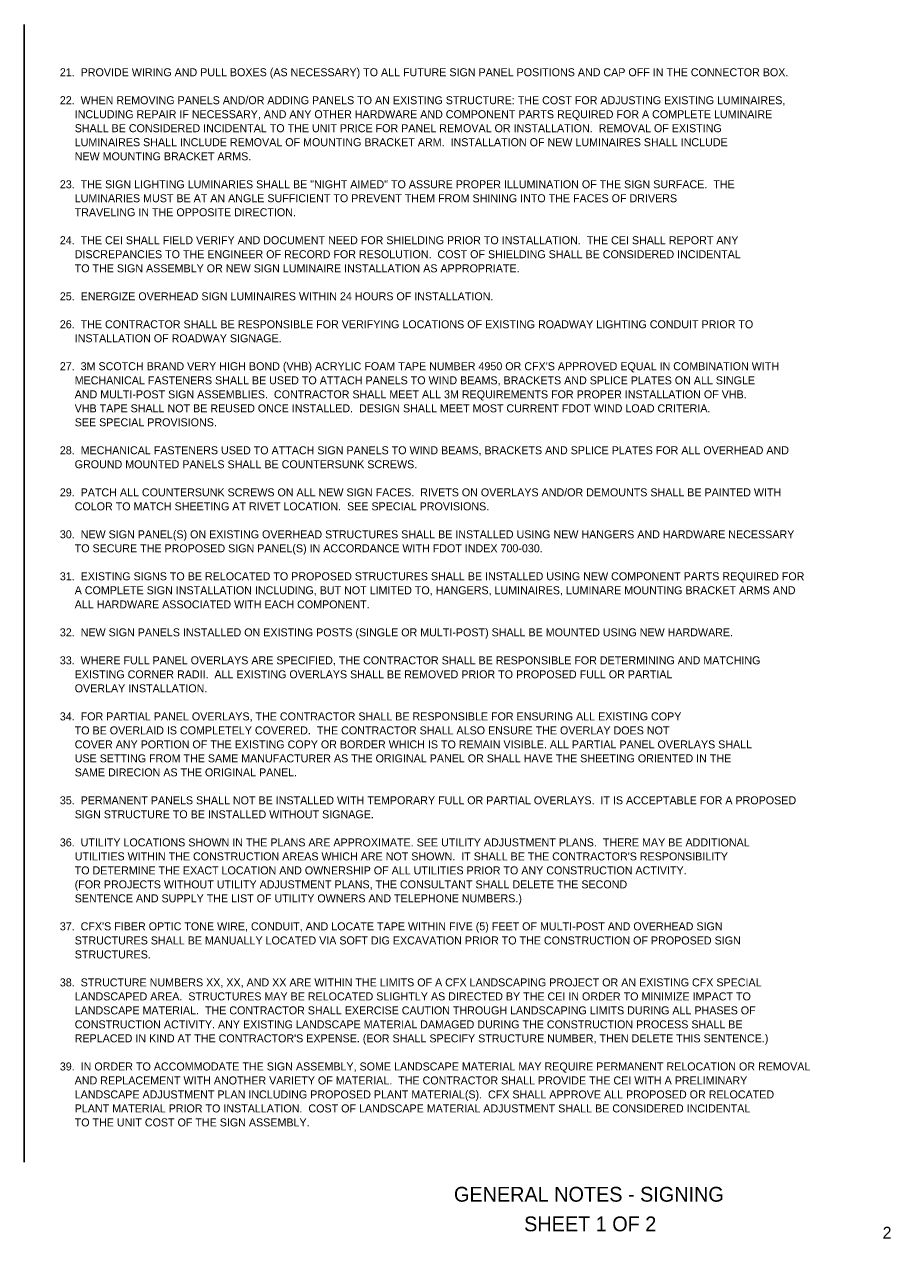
# Model space of a CAD drawing. Extents: x 2479946 to 2481502, y 3680184 to 3681234.
# Drawn here: x 2480771 to 2481502, y 3680210 to 3681234 of the extents above; entities that cross this region are included whole.
import ezdxf

# ---------------------------------------------------------------- set-up
doc = ezdxf.new("R2010")
doc.units = 0
for name, color, linetype in [('NonPlottingEle_dp', 7, 'Continuous'), ('TextLabel', 7, 'Continuous'), ('TextMisc', 7, 'Continuous'), ('TextShtNo', 7, 'Continuous')]:
    doc.layers.add(name, color=color, linetype=linetype)

msp = doc.modelspace()

# ---------------------------------------------------------------- linework, layer by layer
at = {"layer": 'NonPlottingEle_dp'}
msp.add_line((2480770.9, 3680274.2), (2480770.9, 3681234.2), dxfattribs=at)

# ---------------------------------------------------------------- texts
at = {"layer": 'TextLabel'}
for s, p in [('21.  PROVIDE WIRING AND PULL BOXES (AS NECESSARY) TO ALL FUTURE SIGN PANEL POSITIONS AND CAP OFF IN THE CONNECTOR BOX.', (2480800.9, 3681190.4)), ('22.  WHEN REMOVING PANELS AND/OR ADDING PANELS TO AN EXISTING STRUCTURE: THE COST FOR ADJUSTING EXISTING LUMINAIRES,', (2480800.9, 3681166.8)), ('     INCLUDING REPAIR IF NECESSARY, AND ANY OTHER HARDWARE AND COMPONENT PARTS REQUIRED FOR A COMPLETE LUMINAIRE', (2480800.9, 3681155)), ('     SHALL BE CONSIDERED INCIDENTAL TO THE UNIT PRICE FOR PANEL REMOVAL OR INSTALLATION.  REMOVAL OF EXISTING', (2480800.9, 3681143.2)), ('     LUMINAIRES SHALL INCLUDE REMOVAL OF MOUNTING BRACKET ARM.  INSTALLATION OF NEW LUMINAIRES SHALL INCLUDE', (2480800.9, 3681131.4)), ('     NEW MOUNTING BRACKET ARMS.', (2480800.9, 3681119.5)), ('23.  THE SIGN LIGHTING LUMINARIES SHALL BE "NIGHT AIMED" TO ASSURE PROPER ILLUMINATION OF THE SIGN SURFACE.  THE ', (2480800.9, 3681095.9)), ('     LUMINARIES MUST BE AT AN ANGLE SUFFICIENT TO PREVENT THEM FROM SHINING INTO THE FACES OF DRIVERS', (2480800.9, 3681084.1)), ('     TRAVELING IN THE OPPOSITE DIRECTION.', (2480800.9, 3681072.3)), ('24.  THE CEI SHALL FIELD VERIFY AND DOCUMENT NEED FOR SHIELDING PRIOR TO INSTALLATION.  THE CEI SHALL REPORT ANY', (2480800.9, 3681048.7)), ('     DISCREPANCIES TO THE ENGINEER OF RECORD FOR RESOLUTION.  COST OF SHIELDING SHALL BE CONSIDERED INCIDENTAL', (2480800.9, 3681036.9)), ('     TO THE SIGN ASSEMBLY OR NEW SIGN LUMINAIRE INSTALLATION AS APPROPRIATE.', (2480800.9, 3681025)), ('25.  ENERGIZE OVERHEAD SIGN LUMINAIRES WITHIN 24 HOURS OF INSTALLATION.', (2480800.9, 3681001.4)), ('26.  THE CONTRACTOR SHALL BE RESPONSIBLE FOR VERIFYING LOCATIONS OF EXISTING ROADWAY LIGHTING CONDUIT PRIOR TO', (2480800.9, 3680977.8)), ('     INSTALLATION OF ROADWAY SIGNAGE.', (2480800.9, 3680966)), ("27.  3M SCOTCH BRAND VERY HIGH BOND (VHB) ACRYLIC FOAM TAPE NUMBER 4950 OR CFX'S APPROVED EQUAL IN COMBINATION WITH", (2480800.9, 3680942.4)), ('     MECHANICAL FASTENERS SHALL BE USED TO ATTACH PANELS TO WIND BEAMS, BRACKETS AND SPLICE PLATES ON ALL SINGLE', (2480800.9, 3680930.5)), ('     AND MULTI-POST SIGN ASSEMBLIES.  CONTRACTOR SHALL MEET ALL 3M REQUIREMENTS FOR PROPER INSTALLATION OF VHB.', (2480800.9, 3680918.7)), ('     VHB TAPE SHALL NOT BE REUSED ONCE INSTALLED.  DESIGN SHALL MEET MOST CURRENT FDOT WIND LOAD CRITERIA.', (2480800.9, 3680906.9)), ('     SEE SPECIAL PROVISIONS.', (2480800.9, 3680895.1)), ('28.  MECHANICAL FASTENERS USED TO ATTACH SIGN PANELS TO WIND BEAMS, BRACKETS AND SPLICE PLATES FOR ALL OVERHEAD AND', (2480800.9, 3680871.5)), ('     GROUND MOUNTED PANELS SHALL BE COUNTERSUNK SCREWS.', (2480800.9, 3680859.7)), ('29.  PATCH ALL COUNTERSUNK SCREWS ON ALL NEW SIGN FACES.  RIVETS ON OVERLAYS AND/OR DEMOUNTS SHALL BE PAINTED WITH', (2480800.9, 3680836)), ('     COLOR TO MATCH SHEETING AT RIVET LOCATION.  SEE SPECIAL PROVISIONS.', (2480800.9, 3680824.2)), ('30.  NEW SIGN PANEL(S) ON EXISTING OVERHEAD STRUCTURES SHALL BE INSTALLED USING NEW HANGERS AND HARDWARE NECESSARY', (2480800.9, 3680800.6)), ('     TO SECURE THE PROPOSED SIGN PANEL(S) IN ACCORDANCE WITH FDOT INDEX 700-030.', (2480800.9, 3680788.8)), ('31.  EXISTING SIGNS TO BE RELOCATED TO PROPOSED STRUCTURES SHALL BE INSTALLED USING NEW COMPONENT PARTS REQUIRED FOR', (2480800.9, 3680765.2)), ('     A COMPLETE SIGN INSTALLATION INCLUDING, BUT NOT LIMITED TO, HANGERS, LUMINAIRES, LUMINARE MOUNTING BRACKET ARMS AND', (2480800.9, 3680753.4)), ('     ALL HARDWARE ASSOCIATED WITH EACH COMPONENT.', (2480800.9, 3680741.5)), ('32.  NEW SIGN PANELS INSTALLED ON EXISTING POSTS (SINGLE OR MULTI-POST) SHALL BE MOUNTED USING NEW HARDWARE.', (2480800.9, 3680717.9)), ('33.  WHERE FULL PANEL OVERLAYS ARE SPECIFIED, THE CONTRACTOR SHALL BE RESPONSIBLE FOR DETERMINING AND MATCHING', (2480800.9, 3680694.3)), ('     EXISTING CORNER RADII.  ALL EXISTING OVERLAYS SHALL BE REMOVED PRIOR TO PROPOSED FULL OR PARTIAL', (2480800.9, 3680682.5)), ('     OVERLAY INSTALLATION.', (2480800.9, 3680670.7)), ('34.  FOR PARTIAL PANEL OVERLAYS, THE CONTRACTOR SHALL BE RESPONSIBLE FOR ENSURING ALL EXISTING COPY', (2480800.9, 3680647)), ('     TO BE OVERLAID IS COMPLETELY COVERED.  THE CONTRACTOR SHALL ALSO ENSURE THE OVERLAY DOES NOT ', (2480800.9, 3680635.2)), ('     COVER ANY PORTION OF THE EXISTING COPY OR BORDER WHICH IS TO REMAIN VISIBLE. ALL PARTIAL PANEL OVERLAYS SHALL', (2480800.9, 3680623.4)), ('     USE SETTING FROM THE SAME MANUFACTURER AS THE ORIGINAL PANEL OR SHALL HAVE THE SHEETING ORIENTED IN THE', (2480800.9, 3680611.6)), ('     SAME DIRECION AS THE ORIGINAL PANEL.', (2480800.9, 3680599.8)), ('35.  PERMANENT PANELS SHALL NOT BE INSTALLED WITH TEMPORARY FULL OR PARTIAL OVERLAYS.  IT IS ACCEPTABLE FOR A PROPOSED', (2480800.9, 3680576.2)), ('     SIGN STRUCTURE TO BE INSTALLED WITHOUT SIGNAGE.', (2480800.9, 3680564.4)), ('36.  UTILITY LOCATIONS SHOWN IN THE PLANS ARE APPROXIMATE. SEE UTILITY ADJUSTMENT PLANS.  THERE MAY BE ADDITIONAL', (2480800.9, 3680540.7)), ("     UTILITIES WITHIN THE CONSTRUCTION AREAS WHICH ARE NOT SHOWN.  IT SHALL BE THE CONTRACTOR'S RESPONSIBILITY", (2480800.9, 3680528.9)), ('     TO DETERMINE THE EXACT LOCATION AND OWNERSHIP OF ALL UTILITIES PRIOR TO ANY CONSTRUCTION ACTIVITY.', (2480800.9, 3680517.1)), ('     (FOR PROJECTS WITHOUT UTILITY ADJUSTMENT PLANS, THE CONSULTANT SHALL DELETE THE SECOND', (2480800.9, 3680505.3)), ('     SENTENCE AND SUPPLY THE LIST OF UTILITY OWNERS AND TELEPHONE NUMBERS.)', (2480800.9, 3680493.5)), ("37.  CFX'S FIBER OPTIC TONE WIRE, CONDUIT, AND LOCATE TAPE WITHIN FIVE (5) FEET OF MULTI-POST AND OVERHEAD SIGN", (2480800.9, 3680469.9)), ('     STRUCTURES SHALL BE MANUALLY LOCATED VIA SOFT DIG EXCAVATION PRIOR TO THE CONSTRUCTION OF PROPOSED SIGN', (2480800.9, 3680458)), ('     STRUCTURES.', (2480800.9, 3680446.2)), ('38.  STRUCTURE NUMBERS XX, XX, AND XX ARE WITHIN THE LIMITS OF A CFX LANDSCAPING PROJECT OR AN EXISTING CFX SPECIAL', (2480800.9, 3680422.6)), ('     LANDSCAPED AREA.  STRUCTURES MAY BE RELOCATED SLIGHTLY AS DIRECTED BY THE CEI IN ORDER TO MINIMIZE IMPACT TO', (2480800.9, 3680410.8)), ('     LANDSCAPE MATERIAL.  THE CONTRACTOR SHALL EXERCISE CAUTION THROUGH LANDSCAPING LIMITS DURING ALL PHASES OF', (2480800.9, 3680399)), ('     CONSTRUCTION ACTIVITY. ANY EXISTING LANDSCAPE MATERIAL DAMAGED DURING THE CONSTRUCTION PROCESS SHALL BE', (2480800.9, 3680387.2)), ("     REPLACED IN KIND AT THE CONTRACTOR'S EXPENSE. (EOR SHALL SPECIFY STRUCTURE NUMBER, THEN DELETE THIS SENTENCE.)", (2480800.9, 3680375.4)), ('39.  IN ORDER TO ACCOMMODATE THE SIGN ASSEMBLY, SOME LANDSCAPE MATERIAL MAY REQUIRE PERMANENT RELOCATION OR REMOVAL', (2480800.9, 3680351.7)), ('     AND REPLACEMENT WITH ANOTHER VARIETY OF MATERIAL.  THE CONTRACTOR SHALL PROVIDE THE CEI WITH A PRELIMINARY', (2480800.9, 3680339.9)), ('     LANDSCAPE ADJUSTMENT PLAN INCLUDING PROPOSED PLANT MATERIAL(S).  CFX SHALL APPROVE ALL PROPOSED OR RELOCATED', (2480800.9, 3680328.1)), ('     PLANT MATERIAL PRIOR TO INSTALLATION.  COST OF LANDSCAPE MATERIAL ADJUSTMENT SHALL BE CONSIDERED INCIDENTAL', (2480800.9, 3680316.3)), ('     TO THE UNIT COST OF THE SIGN ASSEMBLY.', (2480800.9, 3680304.5))]:
    msp.add_text(s, height=6.75, dxfattribs=at).set_placement(p)
at = {"layer": 'TextMisc'}
for s, p in [('GENERAL NOTES - SIGNING ', (2481133.3, 3680241)), ('      SHEET 1 OF 2      ', (2481164.6, 3680216))]:
    msp.add_text(s, height=12.5, rotation=360, dxfattribs=at).set_placement(p)
at = {"layer": 'TextShtNo'}
msp.add_text('  2  ', height=10, rotation=360, dxfattribs=at).set_placement((2481487.4, 3680209.8))

doc.saveas('drawing.dxf')
